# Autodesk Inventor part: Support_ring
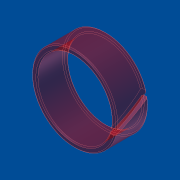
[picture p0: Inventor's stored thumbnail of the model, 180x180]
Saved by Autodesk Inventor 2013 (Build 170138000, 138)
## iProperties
Shininess: 20.0
Length Units: 11269
Angle Units: 11279
Time Units: 11290
Mass Units: 11283
Length Display Precision: 3
Angle Display Precision: 2
Created: 2001-04
Part Number: Support_ring
Material: Standard
Document SubType Name: Modellieren
Designer: dl
Density: 1 g/cm^3
Density: 0.0
Volumn: 0.0
Area: 0.0
PropertySet Name: Model Information
Control State: 0
Master: False
Checked Out: False
Author: dl
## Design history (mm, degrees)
sketch "Sketch1"
  geometry: C1 r 20 at (0, 0); C2 r 17.5 at (0, 0)
  constraints: 2 centre point, 1 coincident
  dimensions: "d0" = 40 diameter of C1; "d1" = 35 diameter of C2
extrude "Extrusion1" new body sketch "Sketch1" distance "d2" = 15; taper "d3" = 0 deg
sketch "Sketch2"
  geometry: L1 (-19.5, 0)-(19.5, 0) reference; L2 (0, 0)-(0, -15); L3 (19.5, -15)-(-19.5, -15) reference; L4 (0, -7.5)-(-4.33, 0); L5 (-5.485, 0)-(-3.175, 0); L6 (-3.175, 0)-(5.485, -15); L7 (5.485, -15)-(3.175, -15); L8 (3.175, -15)-(-5.485, 0)
  constraints: 12 end point, 4 parallel, 2 midpoint, 1 perpendicular, 1 point on line
  dimensions: "d6" = 0 distance from line of L3 L2.end; "d7" = 30 deg angle of L2 L4; "d8" = 2 distance between parallel lines of L6 L8; "d9" = 1 distance between parallel lines of L6 L4 (= 0.5 x d8); "d10" = 0 distance between parallel lines of L1 L5; "d11" = 0 distance from line of L3.start L7
extrude "Extrusion2" cut sketch "Sketch2" stored distance "d12" = 15; taper "d13" = 0 deg
body "Solid1"
chamfer "Chamfer1" distance "d4" = 0.5; stored, may be unused: second distance "d5" = 0.5, angle "d14" = 45 deg
